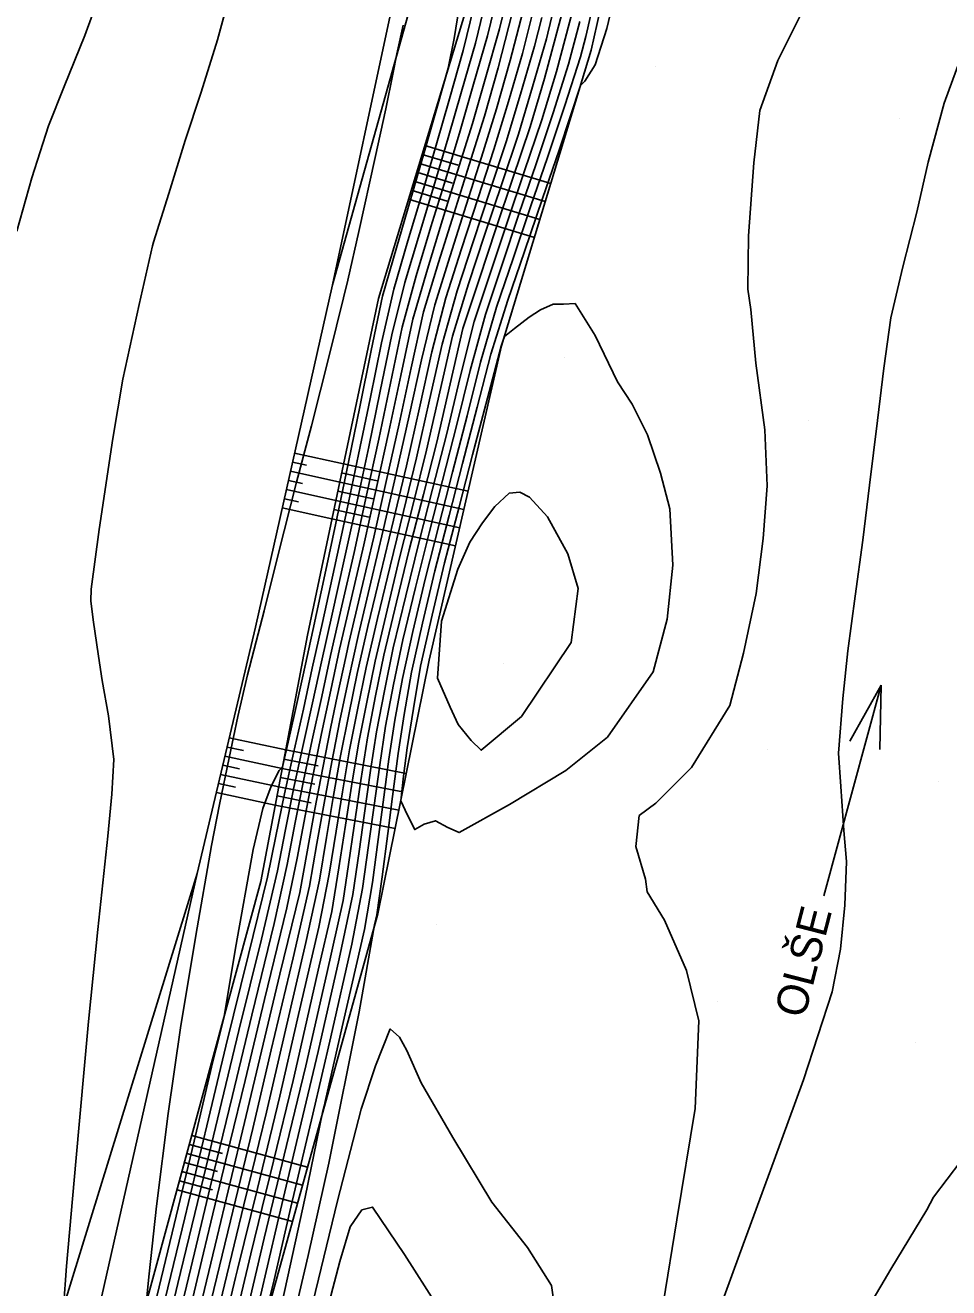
# Model space of a CAD drawing. Extents: x -448957 to -448612, y -1107690 to -1107245.
# Drawn here: x -448719.11 to -448689.52, y -1107510.01 to -1107469.55 of the extents above; entities that cross this region are included whole.
import ezdxf

# ---------------------------------------------------------------- set-up
doc = ezdxf.new("R2010")
doc.units = 0
for name, color, linetype in [('Default', 7, 'Continuous'), ('Vrstva 1', 7, 'Continuous'), ('Vrstva 10', 7, 'Continuous'), ('Vrstva 14', 7, 'Continuous'), ('Vrstva 15', 7, 'Continuous'), ('Vrstva 16', 7, 'Continuous'), ('Vrstva 17', 7, 'Continuous'), ('Vrstva 45', 7, 'Continuous')]:
    doc.layers.add(name, color=color, linetype=linetype)

# ---------------------------------------------------------------- blocks, each defined once
blk = doc.blocks.new('POINT_DISPLAY')
at = {"layer": 'Default'}
blk.add_line((0, 0), (0, 0), dxfattribs=at)
blk = doc.blocks.new('TOK')
at = {"layer": 'Default'}
for p, q in [((-5, 50), (0, 70)), ((0, 0), (0, 70)), ((0, 70), (5, 50))]:
    blk.add_line(p, q, dxfattribs=at)

msp = doc.modelspace()

# ---------------------------------------------------------------- linework, layer by layer
at = {"layer": 'Vrstva 10'}
for p, q in [((-448709.263, -1107477.868), (-448706.695, -1107468.665)), ((-448707.794, -1107478.306), (-448704.993, -1107469.077)), ((-448711.735, -1107488.841), (-448709.263, -1107477.868)), ((-448710.068, -1107489.091), (-448707.794, -1107478.306)), ((-448713.596, -1107496.729), (-448711.735, -1107488.841)), ((-448711.558, -1107496.989), (-448710.068, -1107489.091)), ((-448717.531, -1107514.145), (-448713.596, -1107496.729)), ((-448711.558, -1107496.989), (-448716.314, -1107514.478))]:
    msp.add_line(p, q, dxfattribs=at)
at = {"layer": 'Vrstva 14'}
for p, q in [((-448700.974, -1107470.354), (-448698.327, -1107458.399)), ((-448709.263, -1107477.868), (-448707.256, -1107468.461)), ((-448703.848, -1107479.822), (-448700.974, -1107470.354)), ((-448706.163, -1107489.894), (-448703.848, -1107479.822)), ((-448707.816, -1107498.026), (-448706.163, -1107489.894)), ((-448713.596, -1107496.729), (-448718.86, -1107513.789)), ((-448712.708, -1107515.669), (-448707.816, -1107498.026))]:
    msp.add_line(p, q, dxfattribs=at)
at = {"layer": 'Vrstva 15'}
for p, q in [((-448706.393, -1107473.688), (-448705.24, -1107474.038)), ((-448706.305, -1107473.401), (-448702.271, -1107474.626)), ((-448706.48, -1107473.976), (-448702.445, -1107475.2)), ((-448706.567, -1107474.263), (-448705.414, -1107474.613)), ((-448706.741, -1107474.837), (-448705.588, -1107475.187)), ((-448706.654, -1107474.55), (-448702.619, -1107475.774)), ((-448706.828, -1107475.124), (-448702.794, -1107476.348)), ((-448710.478, -1107483.26), (-448708.911, -1107483.602)), ((-448710.61, -1107483.845), (-448709.034, -1107484.189)), ((-448710.544, -1107483.553), (-448710.094, -1107483.651)), ((-448708.911, -1107483.602), (-448704.919, -1107484.481)), ((-448710.675, -1107484.138), (-448710.223, -1107484.236)), ((-448709.034, -1107484.189), (-448705.053, -1107485.066)), ((-448708.972, -1107483.895), (-448707.835, -1107484.146)), ((-448710.741, -1107484.431), (-448709.158, -1107484.776)), ((-448709.096, -1107484.482), (-448707.962, -1107484.732)), ((-448710.873, -1107485.016), (-448709.282, -1107485.363)), ((-448710.807, -1107484.723), (-448710.353, -1107484.822)), ((-448709.158, -1107484.776), (-448705.188, -1107485.651)), ((-448709.282, -1107485.363), (-448705.322, -1107486.235)), ((-448709.22, -1107485.069), (-448708.089, -1107485.319)), ((-448712.641, -1107492.683), (-448712.117, -1107492.794)), ((-448712.573, -1107492.391), (-448710.763, -1107492.775)), ((-448712.71, -1107492.975), (-448710.874, -1107493.365)), ((-448710.819, -1107493.07), (-448709.718, -1107493.286)), ((-448710.763, -1107492.775), (-448706.902, -1107493.532)), ((-448712.779, -1107493.267), (-448712.247, -1107493.38)), ((-448710.874, -1107493.365), (-448707.022, -1107494.12)), ((-448712.917, -1107493.851), (-448712.377, -1107493.966)), ((-448712.848, -1107493.559), (-448710.986, -1107493.954)), ((-448710.986, -1107493.955), (-448707.141, -1107494.708)), ((-448710.93, -1107493.66), (-448709.832, -1107493.875)), ((-448712.986, -1107494.143), (-448711.097, -1107494.544)), ((-448711.041, -1107494.249), (-448709.945, -1107494.464)), ((-448711.097, -1107494.544), (-448707.261, -1107495.296)), ((-448713.772, -1107505.13), (-448710.068, -1107506.147)), ((-448713.85, -1107505.419), (-448712.793, -1107505.709)), ((-448714.008, -1107505.998), (-448712.951, -1107506.288)), ((-448713.929, -1107505.709), (-448710.228, -1107506.725)), ((-448714.087, -1107506.288), (-448710.388, -1107507.303)), ((-448714.244, -1107506.866), (-448710.549, -1107507.881)), ((-448714.165, -1107506.577), (-448713.11, -1107506.867))]:
    msp.add_line(p, q, dxfattribs=at)
at = {"layer": 'Vrstva 16'}
for points in [[(-448714.623, -1107510.369), (-448713.991, -1107507.763), (-448713.29, -1107504.823), (-448712.681, -1107502.264), (-448711.953, -1107499.331), (-448711.347, -1107496.853), (-448711.08, -1107495.534), (-448710.805, -1107494.182), (-448710.514, -1107492.875), (-448710.197, -1107491.468), (-448709.914, -1107490.158), (-448709.587, -1107488.686), (-448709.2, -1107486.924), (-448708.806, -1107485.105), (-448708.43, -1107483.307), (-448708.062, -1107481.526), (-448707.694, -1107479.724), (-448707.304, -1107478.011), (-448706.845, -1107476.459), (-448706.394, -1107474.939), (-448705.941, -1107473.396), (-448705.514, -1107471.904), (-448705.072, -1107470.358), (-448704.391, -1107467.548)], [(-448713.148, -1107510.415), (-448712.532, -1107507.861), (-448711.819, -1107504.907), (-448711.227, -1107502.381), (-448710.529, -1107499.44), (-448709.998, -1107497.141), (-448709.761, -1107495.775), (-448709.534, -1107494.484), (-448709.288, -1107493.16), (-448709.032, -1107491.833), (-448708.754, -1107490.523), (-448708.435, -1107489.077), (-448708.038, -1107487.401), (-448707.626, -1107485.683), (-448707.22, -1107483.92), (-448706.805, -1107482.068), (-448706.416, -1107480.275), (-448705.99, -1107478.51), (-448705.497, -1107476.937), (-448704.984, -1107475.319), (-448704.488, -1107473.778), (-448704.012, -1107472.229), (-448703.567, -1107470.684), (-448702.956, -1107468.282)], [(-448711.605, -1107510.411), (-448711.023, -1107507.923), (-448710.316, -1107504.947), (-448709.722, -1107502.434), (-448709.046, -1107499.471), (-448708.611, -1107497.405), (-448708.413, -1107496.028), (-448708.239, -1107494.805), (-448708.041, -1107493.428), (-448707.857, -1107492.194), (-448707.598, -1107490.876), (-448707.32, -1107489.504), (-448706.914, -1107487.83), (-448706.488, -1107486.091), (-448706.059, -1107484.421), (-448705.6, -1107482.632), (-448705.186, -1107480.869), (-448704.723, -1107479.041), (-448704.206, -1107477.478), (-448703.651, -1107475.811), (-448703.12, -1107474.253), (-448702.56, -1107472.581), (-448702.084, -1107471.029), (-448701.534, -1107468.943)], [(-448703.598, -1107484.546), (-448703.265, -1107484.508), (-448702.952, -1107484.677), (-448702.374, -1107485.302), (-448701.725, -1107486.492), (-448701.394, -1107487.605), (-448701.622, -1107489.326), (-448703.206, -1107491.697), (-448704.502, -1107492.786), (-448704.823, -1107492.476), (-448705.233, -1107491.961), (-448705.49, -1107491.401), (-448705.903, -1107490.47), (-448705.767, -1107488.651), (-448705.253, -1107486.978), (-448704.862, -1107486.119), (-448704.454, -1107485.491), (-448704.061, -1107484.968), (-448703.598, -1107484.546)], [(-448709.881, -1107512.428), (-448709.034, -1107509.171), (-448708.694, -1107508.057), (-448708.32, -1107507.508), (-448707.978, -1107507.425), (-448706.954, -1107508.948), (-448705.918, -1107510.563)]]:
    msp.add_lwpolyline(points, dxfattribs=at)
at = {"layer": 'Vrstva 17'}
for points in [[(-448713.57, -1107510.912), (-448712.963, -1107508.375), (-448712.254, -1107505.427), (-448711.649, -1107502.875), (-448710.949, -1107499.964), (-448710.313, -1107497.337), (-448710.079, -1107496.035), (-448709.832, -1107494.674), (-448709.576, -1107493.348), (-448709.322, -1107492.033), (-448709.112, -1107491.06), (-448708.83, -1107489.751), (-448708.741, -1107489.337), (-448708.346, -1107487.66), (-448707.944, -1107485.958), (-448707.544, -1107484.172), (-448707.131, -1107482.324), (-448706.747, -1107480.528), (-448706.352, -1107478.733), (-448705.865, -1107477.158), (-448705.368, -1107475.56), (-448704.882, -1107474.024), (-448704.396, -1107472.463), (-448703.953, -1107470.917), (-448703.154, -1107467.775)], [(-448712.475, -1107511.44), (-448711.878, -1107508.923), (-448711.156, -1107505.951), (-448710.523, -1107503.365), (-448710.279, -1107502.293), (-448709.72, -1107499.831), (-448709.29, -1107497.953), (-448709.056, -1107496.557), (-448708.844, -1107495.184), (-448708.65, -1107493.935), (-448708.432, -1107492.578), (-448708.168, -1107491.242), (-448707.901, -1107489.93), (-448707.515, -1107488.296), (-448707.112, -1107486.621), (-448706.67, -1107484.859), (-448706.249, -1107483.166), (-448705.825, -1107481.302), (-448705.421, -1107479.514), (-448704.904, -1107477.84), (-448704.394, -1107476.274), (-448703.83, -1107474.597), (-448703.303, -1107473.039), (-448702.859, -1107471.528), (-448702.408, -1107469.985), (-448702.362, -1107469.805), (-448701.915, -1107467.937)], [(-448707.024, -1107490.483), (-448706.695, -1107488.978), (-448706.293, -1107487.303), (-448705.849, -1107485.537), (-448705.418, -1107483.867), (-448704.95, -1107482.066), (-448704.523, -1107480.351), (-448704.004, -1107478.589), (-448703.478, -1107477.029), (-448702.905, -1107475.341), (-448702.371, -1107473.784), (-448701.822, -1107472.125), (-448701.32, -1107470.564), (-448701.149, -1107469.914), (-448700.7, -1107467.947)], [(-448706.736, -1107490.286), (-448706.383, -1107488.715), (-448705.983, -1107487.039), (-448705.529, -1107485.26), (-448705.097, -1107483.591), (-448704.625, -1107481.784), (-448704.192, -1107480.091), (-448703.644, -1107478.363), (-448703.115, -1107476.805), (-448702.532, -1107475.106), (-448701.996, -1107473.55), (-448701.647, -1107472.487), (-448701.316, -1107471.482), (-448701.183, -1107471.347), (-448700.846, -1107470.824), (-448700.477, -1107469.651), (-448700, -1107467.667)], [(-448717.888, -1107510.638), (-448717.784, -1107509.317), (-448717.486, -1107505.966), (-448717.217, -1107503.009), (-448717.079, -1107501.475), (-448716.78, -1107498.524), (-448716.461, -1107495.537), (-448716.339, -1107494.187), (-448716.269, -1107493.077), (-448716.44, -1107491.681), (-448716.647, -1107490.549), (-448716.759, -1107489.765), (-448716.931, -1107488.603), (-448717.009, -1107487.991), (-448716.996, -1107487.617), (-448716.74, -1107485.708), (-448716.3, -1107482.788), (-448715.979, -1107480.89), (-448715.458, -1107478.494), (-448715.028, -1107476.616), (-448714.998, -1107476.505), (-448714.512, -1107474.94), (-448713.986, -1107473.247), (-448713.476, -1107471.692), (-448712.946, -1107470.02), (-448712.517, -1107468.44)], [(-448715.032, -1107510.861), (-448714.396, -1107508.25), (-448713.698, -1107505.309), (-448713.095, -1107502.761), (-448712.907, -1107502.006), (-448712.735, -1107501.318), (-448712.368, -1107499.125), (-448711.801, -1107495.96), (-448711.493, -1107494.648), (-448711.231, -1107493.932), (-448710.972, -1107493.437), (-448710.866, -1107493.318), (-448710.685, -1107492.527), (-448710.49, -1107491.672), (-448710.207, -1107490.362), (-448709.898, -1107488.948), (-448709.514, -1107487.164), (-448709.125, -1107485.352), (-448708.754, -1107483.551), (-448708.391, -1107481.778), (-448708.027, -1107479.975), (-448707.664, -1107478.228), (-448707.212, -1107476.682), (-448706.772, -1107475.175), (-448706.327, -1107473.63), (-448705.9, -1107472.137), (-448705.553, -1107470.923), (-448705.362, -1107469.978), (-448705.095, -1107468.309)], [(-448714.926, -1107512.839), (-448714.215, -1107509.877), (-448713.585, -1107507.277), (-448712.882, -1107504.337), (-448712.267, -1107501.766), (-448711.543, -1107498.833), (-448711.03, -1107496.649), (-448710.768, -1107495.319), (-448710.498, -1107493.974), (-448710.216, -1107492.664), (-448709.903, -1107491.264), (-448709.621, -1107489.954), (-448709.275, -1107488.424), (-448708.886, -1107486.684), (-448708.488, -1107484.858), (-448708.105, -1107483.062), (-448707.733, -1107481.275), (-448707.361, -1107479.474), (-448706.944, -1107477.795), (-448706.477, -1107476.236), (-448706.015, -1107474.703), (-448705.554, -1107473.163), (-448705.127, -1107471.671), (-448704.686, -1107470.125), (-448704.19, -1107468.08)], [(-448712.04, -1107510.926), (-448711.451, -1107508.423), (-448710.736, -1107505.449), (-448710.123, -1107502.9), (-448709.448, -1107499.943), (-448708.923, -1107497.595), (-448708.754, -1107496.441), (-448708.572, -1107495.209), (-448708.539, -1107494.987), (-448708.356, -1107493.753), (-448708.146, -1107492.385), (-448707.881, -1107491.045), (-448707.617, -1107489.732), (-448707.209, -1107488.036), (-448706.803, -1107486.362), (-448706.351, -1107484.585), (-448705.925, -1107482.914), (-448705.498, -1107481.046), (-448705.083, -1107479.266), (-448704.569, -1107477.702), (-448704.024, -1107476.046), (-448703.495, -1107474.487), (-448702.93, -1107472.809), (-448702.467, -1107471.262), (-448701.727, -1107468.457)], [(-448719.382, -1107476.151), (-448718.893, -1107474.443), (-448718.366, -1107472.777), (-448717.862, -1107471.516), (-448717.198, -1107469.874), (-448716.71, -1107468.518)], [(-448714.516, -1107512.355), (-448713.806, -1107509.385), (-448713.179, -1107506.79), (-448712.473, -1107503.851), (-448711.853, -1107501.269), (-448711.133, -1107498.334), (-448710.713, -1107496.444), (-448710.456, -1107495.104), (-448710.191, -1107493.765), (-448709.918, -1107492.454), (-448709.61, -1107491.059), (-448709.328, -1107489.75), (-448708.963, -1107488.161), (-448708.573, -1107486.444), (-448708.17, -1107484.611), (-448707.781, -1107482.817), (-448707.404, -1107481.023), (-448707.028, -1107479.224), (-448706.583, -1107477.578), (-448706.11, -1107476.013), (-448705.637, -1107474.467), (-448705.168, -1107472.93), (-448704.741, -1107471.439), (-448704.3, -1107469.892), (-448703.99, -1107468.612)], [(-448713.439, -1107512.893), (-448712.727, -1107509.919), (-448712.102, -1107507.347), (-448711.383, -1107504.387), (-448710.805, -1107501.888), (-448710.116, -1107498.944), (-448709.684, -1107496.946), (-448709.455, -1107495.578), (-448709.239, -1107494.301), (-448709.003, -1107492.966), (-448708.744, -1107491.636), (-448708.47, -1107490.325), (-448708.128, -1107488.817), (-448707.729, -1107487.141), (-448707.307, -1107485.409), (-448706.896, -1107483.669), (-448706.478, -1107481.813), (-448706.084, -1107480.021), (-448705.628, -1107478.287), (-448705.129, -1107476.716), (-448704.599, -1107475.078), (-448704.093, -1107473.532), (-448703.627, -1107471.995), (-448703.18, -1107470.451), (-448702.758, -1107468.79)], [(-448694.05, -1107468.796), (-448694.996, -1107470.678), (-448695.57, -1107472.279), (-448695.766, -1107473.956), (-448695.936, -1107476.301), (-448695.952, -1107478.011), (-448695.857, -1107478.655), (-448695.699, -1107480.379), (-448695.416, -1107482.514), (-448695.339, -1107484.314), (-448695.47, -1107486.002), (-448695.688, -1107487.759), (-448696.096, -1107489.668), (-448696.532, -1107491.353), (-448697.766, -1107493.335), (-448698.908, -1107494.475), (-448699.438, -1107494.876), (-448699.545, -1107495.871), (-448699.234, -1107496.911), (-448699.185, -1107497.32), (-448698.631, -1107498.231), (-448697.917, -1107499.842), (-448697.526, -1107501.457), (-448697.639, -1107504.259), (-448698.226, -1107507.828), (-448698.673, -1107510.529)], [(-448713.991, -1107511.408), (-448713.393, -1107508.889), (-448713.159, -1107507.912), (-448712.538, -1107505.329), (-448712.065, -1107503.365), (-448711.438, -1107500.772), (-448710.723, -1107497.836), (-448710.396, -1107496.24), (-448710.144, -1107494.889), (-448709.883, -1107493.556), (-448709.62, -1107492.243), (-448709.317, -1107490.855), (-448709.035, -1107489.546), (-448708.652, -1107487.899), (-448708.259, -1107486.204), (-448707.851, -1107484.364), (-448707.456, -1107482.572), (-448707.075, -1107480.771), (-448706.695, -1107478.974), (-448706.223, -1107477.362), (-448705.742, -1107475.79), (-448705.258, -1107474.231), (-448704.781, -1107472.696), (-448704.355, -1107471.206), (-448703.914, -1107469.66), (-448703.789, -1107469.144)], [(-448715.236, -1107510.516), (-448715.138, -1107509.562), (-448714.901, -1107507.398), (-448714.529, -1107504.429), (-448714.131, -1107501.674), (-448713.642, -1107498.72), (-448713.138, -1107495.841), (-448712.885, -1107494.519), (-448712.578, -1107493.023), (-448712.294, -1107491.706), (-448711.984, -1107490.368), (-448711.648, -1107489.058), (-448711.451, -1107488.313), (-448711.007, -1107486.506), (-448710.414, -1107484.194), (-448709.942, -1107482.383), (-448709.361, -1107480.103), (-448708.912, -1107478.285), (-448708.774, -1107477.72), (-448708.418, -1107476.165), (-448707.894, -1107473.785), (-448707.558, -1107472.224), (-448707.327, -1107471.115), (-448707.198, -1107470.468), (-448707.003, -1107469.546)], [(-448712.971, -1107512.209), (-448712.367, -1107509.677), (-448712.306, -1107509.422), (-448711.672, -1107506.833), (-448710.948, -1107503.867), (-448710.384, -1107501.394), (-448709.703, -1107498.449), (-448709.37, -1107496.752), (-448709.15, -1107495.381), (-448708.945, -1107494.118), (-448708.717, -1107492.772), (-448708.456, -1107491.439), (-448708.185, -1107490.128), (-448707.822, -1107488.557), (-448707.42, -1107486.881), (-448706.989, -1107485.134), (-448706.572, -1107483.417), (-448706.152, -1107481.557), (-448705.753, -1107479.767), (-448705.266, -1107478.064), (-448704.762, -1107476.495), (-448704.215, -1107474.838), (-448703.698, -1107473.285), (-448703.243, -1107471.762), (-448702.794, -1107470.218), (-448702.56, -1107469.297)], [(-448711.449, -1107511.026), (-448711.17, -1107509.897), (-448710.596, -1107507.424), (-448709.897, -1107504.445), (-448709.321, -1107501.969), (-448708.644, -1107498.998), (-448708.299, -1107497.215), (-448708.106, -1107495.837), (-448707.939, -1107494.625), (-448707.748, -1107493.247), (-448707.561, -1107492.008), (-448707.311, -1107490.68), (-448707.007, -1107489.241), (-448706.604, -1107487.566), (-448706.168, -1107485.814), (-448705.739, -1107484.144), (-448705.275, -1107482.349), (-448704.854, -1107480.61), (-448704.364, -1107478.815), (-448703.842, -1107477.253), (-448703.278, -1107475.576), (-448702.746, -1107474.019), (-448702.191, -1107472.353), (-448701.702, -1107470.797), (-448701.341, -1107469.428)], [(-448688.92, -1107470.003), (-448689.664, -1107472.043), (-448690.18, -1107473.934), (-448690.544, -1107475.539), (-448690.989, -1107477.289), (-448691.376, -1107478.924), (-448691.6, -1107480.542), (-448691.804, -1107482.215), (-448692.059, -1107484.293), (-448692.267, -1107486.052), (-448692.515, -1107487.848), (-448692.751, -1107489.6), (-448692.908, -1107491.127), (-448693.047, -1107492.877), (-448692.975, -1107493.943), (-448692.879, -1107495.352), (-448692.795, -1107496.347), (-448692.848, -1107497.748), (-448692.991, -1107499.161), (-448693.256, -1107500.525), (-448694.172, -1107503.346), (-448695.113, -1107505.917), (-448696.223, -1107508.94), (-448697.159, -1107511.516)], [(-448706.449, -1107490.09), (-448706.071, -1107488.452), (-448705.673, -1107486.776), (-448705.21, -1107484.983), (-448704.776, -1107483.314), (-448704.3, -1107481.501), (-448703.861, -1107479.832), (-448703.808, -1107479.671), (-448703.757, -1107479.523), (-448703.428, -1107479.27), (-448702.964, -1107478.907), (-448702.604, -1107478.669), (-448702.197, -1107478.489), (-448701.857, -1107478.489), (-448701.49, -1107478.472), (-448700.847, -1107479.488), (-448700.137, -1107480.974), (-448699.662, -1107481.697), (-448699.167, -1107482.679), (-448698.749, -1107483.903), (-448698.455, -1107485.045), (-448698.361, -1107486.857), (-448698.54, -1107488.584), (-448698.987, -1107490.266), (-448700.449, -1107492.363), (-448701.789, -1107493.438), (-448703.597, -1107494.521), (-448705.204, -1107495.423), (-448705.564, -1107495.264), (-448705.966, -1107495.042), (-448706.324, -1107495.15), (-448706.631, -1107495.326), (-448706.861, -1107494.859), (-448707.079, -1107494.401), (-448706.984, -1107493.618), (-448706.869, -1107492.701), (-448706.673, -1107491.451), (-448706.449, -1107490.09)], [(-448710.876, -1107512.537), (-448710.047, -1107508.971), (-448709.386, -1107506.017), (-448708.412, -1107501.169), (-448707.915, -1107498.383), (-448707.84, -1107498.054), (-448707.676, -1107496.835), (-448707.49, -1107495.455), (-448707.34, -1107494.265), (-448707.162, -1107492.883), (-448706.969, -1107491.636), (-448706.736, -1107490.286)], [(-448711.025, -1107511.152), (-448710.144, -1107507.109), (-448709.582, -1107504.396), (-448709.535, -1107504.191), (-448709.477, -1107503.943), (-448708.921, -1107501.504), (-448708.242, -1107498.526), (-448707.987, -1107497.025), (-448707.798, -1107495.646), (-448707.64, -1107494.445), (-448707.455, -1107493.065), (-448707.265, -1107491.822), (-448707.024, -1107490.483)], [(-448709.982, -1107510.835), (-448709.1, -1107507.224), (-448708.347, -1107504.287), (-448707.889, -1107502.895), (-448707.414, -1107501.716), (-448707.121, -1107501.975), (-448706.885, -1107502.405), (-448706.419, -1107503.445), (-448705.41, -1107505.196), (-448704.156, -1107507.264), (-448703.017, -1107508.719), (-448702.247, -1107509.941), (-448701.718, -1107513.715)], [(-448689.134, -1107505.956), (-448690.006, -1107507.109), (-448690.222, -1107507.516), (-448691.378, -1107509.412), (-448692.824, -1107511.885)]]:
    msp.add_lwpolyline(points, dxfattribs=at)

# ---------------------------------------------------------------- block references
at = {"layer": 'Vrstva 1', "xscale": 0.1, "yscale": 0.10000000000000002}
for p in [(-448700.974, -1107470.354), (-448709.263, -1107477.868), (-448709.263, -1107477.868), (-448707.794, -1107478.306), (-448703.848, -1107479.822), (-448711.735, -1107488.841), (-448710.068, -1107489.091), (-448706.163, -1107489.894), (-448713.596, -1107496.729), (-448711.558, -1107496.989), (-448707.816, -1107498.026)]:
    msp.add_blockref('POINT_DISPLAY', p, dxfattribs=at)
at = {"layer": 'Vrstva 14', "xscale": 0.1, "yscale": 0.10000000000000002}
for p in [(-448698.923, -1107470.862), (-448691.112, -1107472.54), (-448714.981, -1107476.531), (-448701.845, -1107480.2), (-448694.015, -1107482.232), (-448703.784, -1107489.991), (-448695.321, -1107492.775), (-448689.849, -1107493.779), (-448705.939, -1107498.379), (-448696.913, -1107500.836), (-448690.585, -1107502.138)]:
    msp.add_blockref('POINT_DISPLAY', p, dxfattribs=at)
at = {"layer": 'Vrstva 45', "xscale": 0.1, "yscale": 0.10000000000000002, "rotation": -15.24572582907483}
msp.add_blockref('TOK', (-448693.525, -1107497.449), dxfattribs=at)

# ---------------------------------------------------------------- texts
at = {"layer": 'Vrstva 45'}
msp.add_text('OLŠE', height=1, rotation=75.591, dxfattribs=at).set_placement((-448694.144, -1107501.406))

doc.saveas('drawing.dxf')
